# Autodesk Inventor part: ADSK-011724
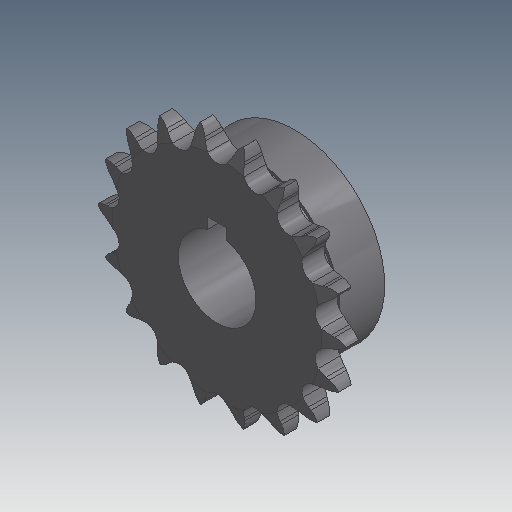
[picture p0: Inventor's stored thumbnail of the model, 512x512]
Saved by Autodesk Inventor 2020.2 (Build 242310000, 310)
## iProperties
Created: 1999-12
Part Number: ADSK-011724
Material: Acier (alliage faible hypertrempé)
Description: SPROCKET,B,40B18,1.00B,0.25 KEY
Document SubType Name: Modeling
Designer: gpurviance
Density: 7.84 g/cm^3
Appearance: Metal-Steel(Polish)
Mass: 495.613 g
Surface Area: 150.654 cm^2
Volume: 63.2159 cm^3
Control State: 0
Master: False
Checked Out: False
Shininess: 0.0
Length Units: 11272
Angle Units: 11279
Time Units: 11290
Mass Units: 11286
Length Display Precision: 3
Angle Display Precision: 2
Compacted: True
Dimensions: 3,1x1x3,2 in
Mass: 1,093 lb
VLT_Material: Acier (alliage faible hypertrempé)
Density: 0.0
Volumn: 0.0
Area: 0.0
PropertySet Name: Model Information
Author: gpurviance
Revision Number: -
Title: SPROCKET,B,40B18,1.00B,0.25 KEY
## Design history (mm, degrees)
node "Solide1"
node "Corps solides"
node "Corps surfaciques"
node "Sprocket blank" dims "d1" = 7.2136 (= thk), "d2" = 0
node "Half of tooth shape" dims "d15" = 7.2136 (= thk), "d16" = 0
node "Sprocket centerline"
node "Hub" dims "d28" = 18.1864 (= hubthk), "d29" = 0
node "Bore extrusion" dims "d31" = 18.1864 (= hubthk), "d32" = 0 (computed from Taper)
node "Mirror of tooth half"
node "tooth array" dims "d17" = 180 (= N_1), "d19" = 20 deg (computed from N_1)
node "Revolution2" dims "d46" = 90 deg
node "Extrusion6" dims "d53" = 25.4, "d54" = 0
workplane "Arbeitsebene1"
sketch "Sketch1"
  geometry: C1 r 32.606 at (0, 0)
  constraints: 1 centre point
  dimensions: "d0" = 32.60579 radius of C1 (computed from N_1, Pitch, Dr)
sketch "Sketch2" dims "d5" = 7.9248 (= Dr)
  geometry: L1 (0, 39.127)-(0, 0); L2 (0, 0)-(13.382, 36.767); L3 (0, 0)-(6.794, 38.533); L4 (0, 36.568)-(-7.642, 36.568); L5 (3.108, 34.111)-(-4.973, 40.5); L6 (-4.973, 40.5)-(7.539, 35.074); L7 (-11.233, 44.251)-(20.947, 30.296); L8 (4.479, 36.402)-(4.857, 37.274); L9 (24.139, 65.256)-(10.873, 34.665); L10 (7.052, 39.994)-(5.662, 32.11); C1 r 32.606 at (0, 0) reference; C2 r 43.904 at (0, 0); A1 r 3.962 centre (0, 36.568) between (0, 32.606) and (3.108, 34.111); A2 r 10.302 centre (-4.973, 40.5) between (3.108, 34.111) and (4.479, 36.402); A3 r 6.558 centre (10.873, 34.665) between (7.052, 39.994) and (4.857, 37.274); A4 r 32.606 centre (0, 0) between (5.662, 32.11) and (0, 32.606)
  constraints: 20 end point, 8 point on circle, 5 centre point, 5 point on line, 4 coincident, 2 equal length, 2 tangent, 1 collinear, 1 horizontal, 1 midpoint, 1 parallel, 1 vertical, 1 vertical alignment, 3 other
  dimensions: "d7" = 10 deg angle of L3 L1 (computed from N_1); "d8" = 10 deg angle of L2 L3 (= d7); "d9" = 38.3333 deg angle of L5 L4 (computed from N_1); "d10" = 14.8889 deg angle of L6 L5 (computed from N_1); "d11" = 6.33984 distance of L4.start L5.end (= 0.8 x Dr); "d12" = 0.95056 distance between parallel lines of L6 L7 (computed from Dr, N_1); "d13" = 39.12695 distance of L1.end L2.end (= 1.2 x d0); "d14" = 6.55751 distance between parallel lines of L9 L8 (computed from N_1, Dr); "d33" = 32.60579 radius of A4 (= d0); "d48" = 87.8078 diameter of C2
sketch "Sketch5"
  geometry: C1 r 32.606 at (0, 0) reference; C2 r 29.369 at (0, 0)
  constraints: 1 centre point, 1 coincident
  dimensions: "d27" = 58.7375 diameter of C2 (= hubdia)
sketch "Sketch6"
  geometry: C1 r 29.369 at (0, 0) reference; C2 r 12.7 at (0, 0)
  constraints: 1 centre point, 1 coincident
  dimensions: "d30" = 25.4 diameter of C2 (= bore)
sketch "Sketch7"
  geometry: L1 (7.214, -8.005)-(7.214, 0) reference; L2 (0, 0)-(7.214, 0) reference; L3 (0, -8.005)-(0, 0) reference; L4 (1.575, 0)-(0, -6.35); L5 (5.639, 0)-(7.214, -6.35); L6 (0, 0)-(-3.607, 0); L7 (-3.607, 0)-(-3.607, -12.121); L8 (-3.607, -12.121)-(0, -12.121); L9 (0, -12.121)-(0, 0); L10 (-0.721, -40.611)-(9.378, -40.611) reference
  constraints: 12 end point, 4 point on line, 2 parallel, 1 horizontal, 1 perpendicular
  dimensions: "d40" = 1.5748 distance from line of L4.start L3 (= G); "d41" = 1.5748 distance from line of L5.start L1 (= G); "d42" = 6.35 distance from line of L5.end L2 (= h); "d43" = 6.35 distance from line of L4.end L2 (= h); "d44" = 5.77088 distance from line of L8 L5.end (= 0.8 x thk); "d45" = 3.6068 distance between parallel lines of L3 L7 (= 0.5 x thk)
sketch "Sketch8"
  geometry: L1 (0, 63.99)-(0, -47.993) reference; L2 (-48.733, 0)-(64.977, 0) reference; L3 (-3.175, 9.525)-(3.175, 9.525); L4 (3.175, 9.525)-(3.175, 15.875); L5 (3.175, 15.875)-(-3.175, 15.875); L6 (-3.175, 15.875)-(-3.175, 9.525)
  constraints: 8 end point, 2 parallel, 1 horizontal, 1 perpendicular
  dimensions: "d49" = 6.35 distance between parallel lines of L3 L5 (= Key); "d50" = 3.175 distance between parallel lines of L1 L4 (= 0.5 x Key); "d51" = 6.35 distance between parallel lines of L4 L6 (= Key); "d52" = 15.875 distance between parallel lines of L2 L5 (= 0.5 x bore + 0.5 x Key)
other parameters: "Pitch" = 12.7 [user parameter; used in 1 equation term], "Dr" = 7.9248 [user parameter; used in 5 equation terms], "thk" = 7.2136 [user parameter; used in 5 equation terms], "h" = 6.35 [user parameter; used in 2 equation terms], "G" = 1.5748 [user parameter; used in 2 equation terms], "hubdia" = 58.7375 [user parameter; used in 1 equation term], "hubthk" = 18.1864 (computed from thk) [user parameter; used in 2 equation terms], "bore" = 25.4 [user parameter; used in 2 equation terms], "Taper" = 0 [user parameter; used in 1 equation term], "Key" = 6.35 [user parameter; used in 4 equation terms]
